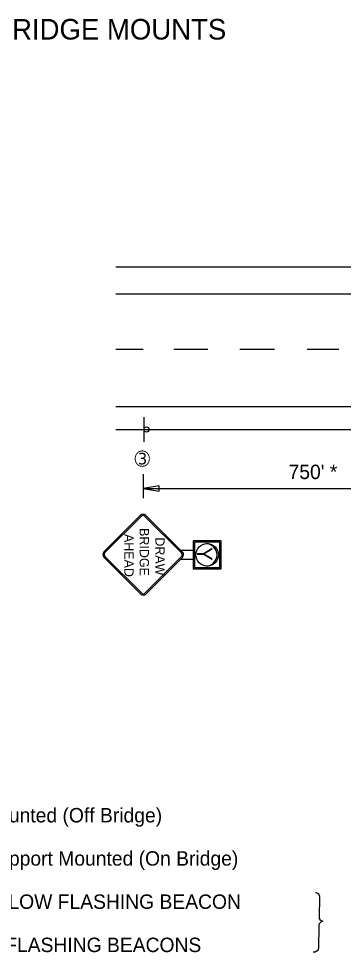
# Model space of a CAD drawing. Extents: x 10000 to 10825, y 10000 to 10530.
# Drawn here: x 10405.7 to 10484.5, y 10277.1 to 10503.9 of the extents above; entities that cross this region are included whole.
import ezdxf

# ---------------------------------------------------------------- set-up
doc = ezdxf.new("R2010")
doc.units = 0
for name, color, linetype in [('Default', 7, 'Continuous'), ('Dimension', 7, 'Continuous'), ('Symbols', 7, 'Continuous'), ('TextStructures', 7, 'Continuous')]:
    doc.layers.add(name, color=color, linetype=linetype)

msp = doc.modelspace()

# ---------------------------------------------------------------- linework, layer by layer
at = {"layer": 'Default'}
for p, q in [((10429.35, 10443.61), (10774.15, 10443.61)), ((10429.35, 10437.05), (10774.15, 10437.05)), ((10429.35, 10423.67), (10435.92, 10423.67)), ((10443.44, 10423.67), (10451.65, 10423.67)), ((10459.4, 10423.67), (10467.82, 10423.67)), ((10475.76, 10423.67), (10483.44, 10423.67)), ((10429.35, 10409.73), (10774.15, 10409.73)), ((10436.13, 10407.1), (10436.13, 10401.16)), ((10436.13, 10406.84), (10436.13, 10401.44)), ((10429.35, 10404.14), (10774.15, 10404.14)), ((10435.93, 10393.3), (10435.93, 10387.48)), ((10435.93, 10389.81), (10521.83, 10389.81)), ((10426.44, 10374.44), (10435.27, 10383.25)), ((10426.67, 10374.21), (10435.49, 10383.02)), ((10436.39, 10383.02), (10445.27, 10374.14)), ((10436.62, 10383.25), (10445.5, 10374.37)), ((10448.06, 10377.1), (10448.06, 10370.25)), ((10454.91, 10377.1), (10448.06, 10377.1)), ((10454.91, 10370.25), (10454.91, 10377.1)), ((10439.49, 10375.3), (10439.49, 10375.29)), ((10445.02, 10374.85), (10448.05, 10374.85)), ((10448.4, 10376.76), (10448.4, 10370.6)), ((10454.56, 10376.76), (10448.4, 10376.76)), ((10454.56, 10370.6), (10454.56, 10376.76)), ((10426.44, 10373.08), (10435.33, 10364.2)), ((10426.67, 10373.31), (10435.56, 10364.42)), ((10436.45, 10364.42), (10445.27, 10373.24)), ((10436.68, 10364.2), (10445.5, 10373.01)), ((10445.08, 10372.59), (10448.05, 10372.59)), ((10448.06, 10370.25), (10454.91, 10370.25)), ((10448.4, 10370.6), (10454.56, 10370.6))]:
    msp.add_line(p, q, dxfattribs=at)
for centre, radius in [((10436.76, 10404.13), 0.637), ((10451.48, 10373.68), 2.74)]:
    msp.add_circle(centre, radius, dxfattribs=at)
for centre, radius, start, end in [((10435.94, 10382.58), 0.958, 44.9847, 134.9857), ((10435.94, 10382.58), 0.635, 44.9847, 134.9857), ((10451.14, 10373.68), 2.74, 273.5833, 86.4167), ((10427.12, 10373.76), 0.958, 134.9857, 224.9846), ((10427.12, 10373.76), 0.635, 134.9857, 224.9846), ((10444.82, 10373.69), 0.635, 314.9852, 44.9843), ((10444.82, 10373.69), 0.958, 314.9852, 44.9843), ((10436, 10364.87), 0.958, 224.9848, 314.9852), ((10436, 10364.87), 0.635, 224.9848, 314.9852)]:
    msp.add_arc(centre, radius, start, end, dxfattribs=at)
at = {"layer": 'Dimension'}
msp.add_lwpolyline([(10435.93, 10389.81), (10439.84, 10389.15), (10439.84, 10390.47)], close=True, dxfattribs=at)
at = {"layer": 'Symbols'}
for points in [[(10478.7, 10291.03), (10478.72, 10290.51), (10478.64, 10285.69), (10478.68, 10285.31), (10478.95, 10284.96), (10479.29, 10284.75), (10479.54, 10284.67), (10479.19, 10284.49), (10478.9, 10284.31), (10478.73, 10284.1), (10478.64, 10283.92), (10478.59, 10283.76), (10478.57, 10283.48), (10478.5, 10278.2), (10478.4, 10277.81), (10478.15, 10277.47), (10477.94, 10277.28), (10477.69, 10277.18), (10477.49, 10277.12), (10477.24, 10277.14)], [(10478.8, 10290.82), (10478.7, 10291.03), (10478.59, 10291.21), (10478.37, 10291.4), (10478.14, 10291.52), (10477.98, 10291.55), (10477.78, 10291.55)]]:
    msp.add_lwpolyline(points, dxfattribs=at)

# ---------------------------------------------------------------- texts
at = {"layer": 'Default'}
for s, p in [('BRIDGE', (10435.1, 10380.18)), ('AHEAD', (10431.4, 10378.75)), ('DRAW', (10438.91, 10377.93))]:
    msp.add_text(s, height=2.265, rotation=270, dxfattribs=at).set_placement(p)
at = {"layer": 'TextStructures'}
for s, height, rotation, p in [('TYPICAL BRIDGE MOUNTS', 5, 0.0007, (10369.95, 10498.86)), ("750' *", 3.5, 0.0007, (10471.25, 10392.09)), ('Y', 3.78, 270, (10449, 10375.59))]:
    msp.add_text(s, height=height, rotation=rotation, dxfattribs=at).set_placement(p)
for s, p in [('➂', (10433.89, 10395.3)), ('Mast Arm Mounted (Off Bridge)', (10375.54, 10308.68)), ('Monotube Support Mounted (On Bridge)', (10375.54, 10298.18)), ('DRAWBRIDGE AHEAD SIGN WITH YELLOW FLASHING BEACON', (10317.44, 10287.68)), ('STOP HERE ON RED SIGN WITH RED FLASHING BEACONS', (10317.44, 10277.18))]:
    msp.add_text(s, height=3.5, dxfattribs=at).set_placement(p)

doc.saveas('drawing.dxf')
